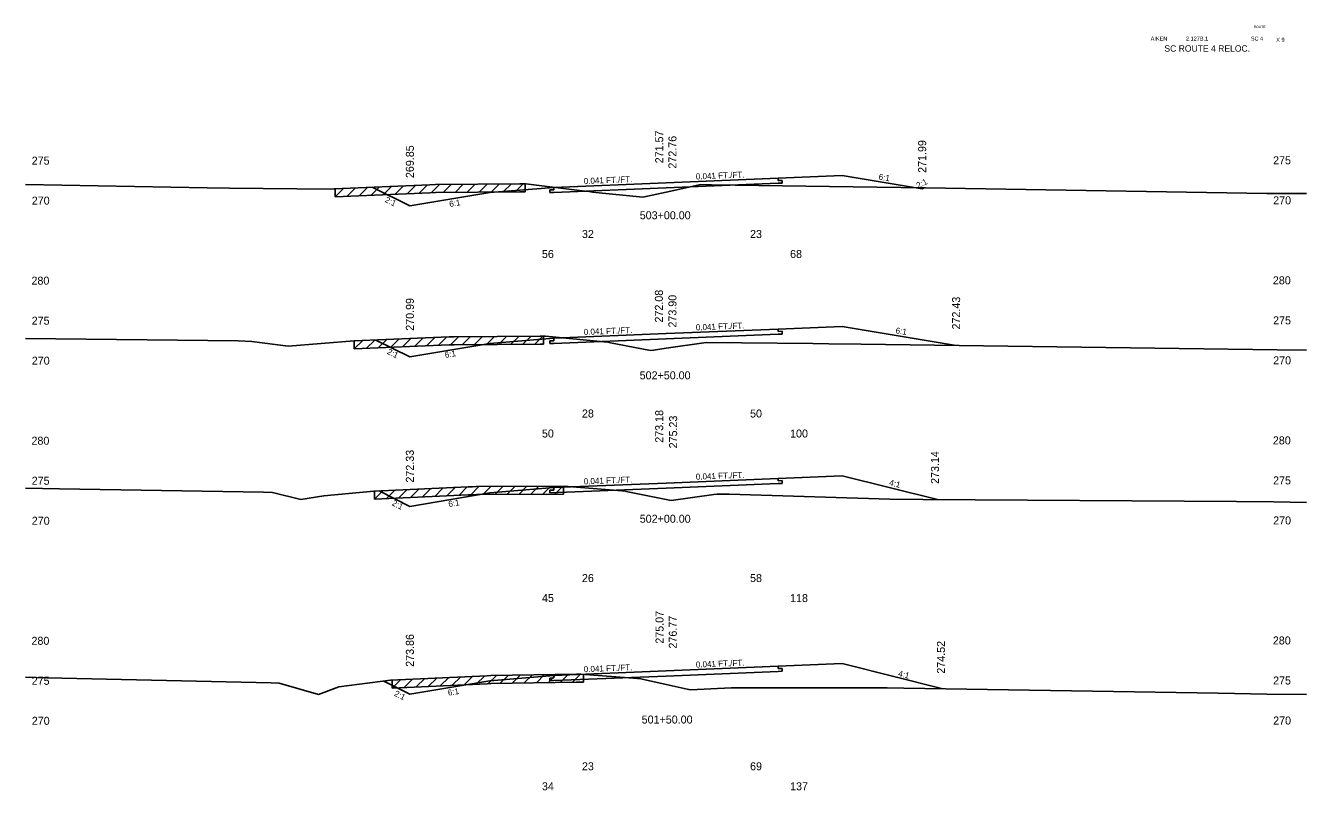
# Model space of a CAD drawing. Extents: x 2967 to 4323, y -3677 to -817.
# Drawn here: x 3188.8 to 3348.8, y -2753 to -2657.5 of the extents above; entities that cross this region are included whole.
import ezdxf

# ---------------------------------------------------------------- set-up
doc = ezdxf.new("R2010")
doc.units = 0
for name, color, linetype in [('Level 1', 7, 'Continuous'), ('Level 10', 7, 'Continuous'), ('Level 11', 7, 'Continuous'), ('Level 12', 7, 'Continuous'), ('Level 20', 7, 'Continuous'), ('Level 3', 7, 'Continuous'), ('Level 32', 7, 'Continuous'), ('Level 33', 7, 'Continuous'), ('Level 59', 7, 'Continuous'), ('Level 6', 7, 'Continuous'), ('Level 60', 7, 'Continuous'), ('Level 61', 7, 'Continuous'), ('Level 7', 7, 'Continuous')]:
    doc.layers.add(name, color=color, linetype=linetype)

msp = doc.modelspace()

# ---------------------------------------------------------------- linework, layer by layer
at = {"layer": 'Level 11'}
for p, q in [((3282.76, -2676.81), (3282.76, -2676.51)), ((3283.26, -2676.79), (3282.76, -2676.81)), ((3283.26, -2677.13), (3283.26, -2676.79)), ((3254.76, -2677.96), (3254.26, -2677.98)), ((3254.26, -2677.98), (3254.26, -2678.32)), ((3254.26, -2678.32), (3254.76, -2678.3)), ((3254.76, -2677.66), (3254.76, -2677.96)), ((3282.76, -2677.15), (3283.26, -2677.13)), ((3282.76, -2695.67), (3282.76, -2695.37)), ((3283.26, -2695.65), (3282.76, -2695.67)), ((3282.76, -2696.01), (3283.26, -2695.99)), ((3283.26, -2695.99), (3283.26, -2695.65)), ((3254.76, -2696.82), (3254.26, -2696.84)), ((3254.26, -2696.84), (3254.26, -2697.18)), ((3254.26, -2697.18), (3254.76, -2697.16)), ((3254.76, -2696.52), (3254.76, -2696.82)), ((3254.76, -2715.18), (3254.76, -2715.48)), ((3282.76, -2714.33), (3282.76, -2714.03)), ((3283.26, -2714.31), (3282.76, -2714.33)), ((3282.76, -2714.67), (3283.26, -2714.65)), ((3283.26, -2714.65), (3283.26, -2714.31)), ((3254.76, -2715.48), (3254.26, -2715.5)), ((3254.26, -2715.5), (3254.26, -2715.84)), ((3282.76, -2737.8), (3282.76, -2737.5)), ((3254.76, -2738.95), (3254.26, -2738.97)), ((3254.26, -2738.97), (3254.26, -2739.31)), ((3254.76, -2738.65), (3254.76, -2738.95)), ((3283.26, -2737.78), (3282.76, -2737.8)), ((3282.76, -2738.14), (3283.26, -2738.12)), ((3283.26, -2738.12), (3283.26, -2737.78)), ((3254.26, -2739.31), (3254.76, -2739.29))]:
    msp.add_line(p, q, dxfattribs=at)
at = {"layer": 'Level 12'}
for p, q in [((3268.76, -2677.72), (3254.76, -2678.3)), ((3282.76, -2677.15), (3268.76, -2677.72)), ((3268.76, -2696.58), (3254.76, -2697.16)), ((3282.76, -2696.01), (3268.76, -2696.58)), ((3268.76, -2715.25), (3282.76, -2714.67)), ((3254.26, -2715.84), (3268.76, -2715.25)), ((3254.76, -2739.29), (3268.76, -2738.72)), ((3268.76, -2738.72), (3282.76, -2738.14))]:
    msp.add_line(p, q, dxfattribs=at)
at = {"layer": 'Level 59'}
for p, q in [((3268.76, -2677.08), (3282.76, -2676.51)), ((3254.76, -2677.66), (3268.76, -2677.08)), ((3254.76, -2696.52), (3268.76, -2695.94)), ((3268.76, -2695.94), (3282.76, -2695.37)), ((3254.76, -2715.18), (3268.76, -2714.61)), ((3268.76, -2714.61), (3282.76, -2714.03)), ((3268.76, -2738.08), (3282.76, -2737.5)), ((3254.76, -2738.65), (3268.76, -2738.08))]:
    msp.add_line(p, q, dxfattribs=at)
at = {"layer": 'Level 6'}
for p, q in [((3282.76, -2676.51), (3290.76, -2676.18)), ((3246.76, -2678.32), (3254.76, -2677.66)), ((3282.76, -2695.37), (3290.76, -2695.04)), ((3246.76, -2697.18), (3254.76, -2696.52)), ((3246.76, -2715.85), (3254.76, -2715.18)), ((3282.76, -2714.03), (3290.76, -2713.71)), ((3282.76, -2737.5), (3290.76, -2737.17)), ((3246.76, -2739.32), (3254.76, -2738.65))]:
    msp.add_line(p, q, dxfattribs=at)
at = {"layer": 'Level 60'}
for p, q in [((3188.76, -2677.31), (3211.45, -2677.73)), ((3211.45, -2677.73), (3214.24, -2677.78)), ((3214.24, -2677.78), (3226.86, -2677.87)), ((3226.86, -2677.87), (3227.3, -2677.84)), ((3227.3, -2677.84), (3239.25, -2677.35)), ((3239.25, -2677.35), (3239.97, -2677.31)), ((3239.97, -2677.31), (3250.48, -2677.21)), ((3250.48, -2677.21), (3251.26, -2677.21)), ((3251.26, -2677.21), (3258.6, -2678.12)), ((3258.6, -2678.12), (3259.17, -2678.18)), ((3259.17, -2678.18), (3259.56, -2678.25)), ((3259.56, -2678.25), (3265.87, -2678.87)), ((3266.45, -2678.78), (3268.76, -2678.28)), ((3268.76, -2678.28), (3273.12, -2677.31)), ((3273.12, -2677.31), (3274.44, -2677.33)), ((3274.44, -2677.33), (3295.1, -2677.65)), ((3295.1, -2677.65), (3301.17, -2677.73)), ((3301.17, -2677.73), (3343.8, -2678.42)), ((3265.87, -2678.87), (3266.45, -2678.78)), ((3343.8, -2678.42), (3348.76, -2678.45)), ((3188.76, -2696.54), (3215.33, -2696.86)), ((3215.33, -2696.86), (3217.01, -2696.91)), ((3217.01, -2696.91), (3221.55, -2697.5)), ((3221.55, -2697.5), (3229.8, -2696.86)), ((3229.8, -2696.86), (3241.67, -2696.35)), ((3241.67, -2696.35), (3242.3, -2696.32)), ((3242.3, -2696.32), (3253.03, -2696.27)), ((3253.03, -2696.27), (3253.7, -2696.27)), ((3253.7, -2696.27), (3261.01, -2696.98)), ((3261.01, -2696.98), (3261.48, -2697.02)), ((3261.48, -2697.02), (3261.84, -2697.09)), ((3261.84, -2697.09), (3266.83, -2698.04)), ((3268.76, -2697.77), (3273.76, -2697.05)), ((3273.76, -2697.05), (3287.11, -2697.17)), ((3287.11, -2697.17), (3289.11, -2697.23)), ((3289.11, -2697.23), (3293.14, -2697.26)), ((3293.14, -2697.26), (3345.12, -2697.95)), ((3266.83, -2698.04), (3267.21, -2697.99)), ((3267.21, -2697.99), (3268.76, -2697.77)), ((3345.12, -2697.95), (3348.76, -2698.02)), ((3232.25, -2715.63), (3244.06, -2715.1)), ((3244.06, -2715.1), (3244.59, -2715.07)), ((3244.59, -2715.07), (3245.07, -2715.06)), ((3245.07, -2715.06), (3256.03, -2714.98)), ((3256.03, -2714.98), (3263.25, -2715.6)), ((3188.76, -2715.26), (3193, -2715.33)), ((3193, -2715.33), (3218.48, -2715.75)), ((3218.48, -2715.75), (3219.62, -2715.78)), ((3219.62, -2715.78), (3223.15, -2716.67)), ((3223.15, -2716.67), (3226.03, -2716.2)), ((3226.03, -2716.2), (3232.25, -2715.63)), ((3263.25, -2715.6), (3263.66, -2715.63)), ((3263.66, -2715.63), (3264.01, -2715.71)), ((3264.01, -2715.71), (3268.76, -2716.66)), ((3268.76, -2716.66), (3269.39, -2716.79)), ((3269.39, -2716.79), (3274.75, -2716.02)), ((3274.75, -2716.02), (3275.13, -2716.01)), ((3275.13, -2716.01), (3276.63, -2716.01)), ((3276.63, -2716.01), (3296.71, -2716.61)), ((3296.71, -2716.61), (3300.85, -2716.67)), ((3300.85, -2716.67), (3340.02, -2716.91)), ((3340.02, -2716.91), (3344.7, -2716.97)), ((3344.7, -2716.97), (3348.76, -2717.05)), ((3188.76, -2738.88), (3191.4, -2738.94)), ((3191.4, -2738.94), (3219.45, -2739.58)), ((3234.34, -2739.24), (3246.4, -2738.68)), ((3246.4, -2738.68), (3246.87, -2738.65)), ((3246.87, -2738.65), (3257.58, -2738.47)), ((3257.58, -2738.47), (3258.13, -2738.47)), ((3258.13, -2738.47), (3265.2, -2739.04)), ((3265.2, -2739.04), (3265.6, -2739.07)), ((3265.6, -2739.07), (3268.76, -2739.77)), ((3219.45, -2739.58), (3220.43, -2739.6)), ((3220.43, -2739.6), (3225.34, -2741.05)), ((3225.34, -2741.05), (3227.89, -2740.09)), ((3227.89, -2740.09), (3234.34, -2739.24)), ((3268.76, -2739.77), (3271.42, -2740.36)), ((3271.42, -2740.36), (3271.81, -2740.44)), ((3271.81, -2740.44), (3276.88, -2740.21)), ((3276.88, -2740.21), (3277.32, -2740.2)), ((3277.32, -2740.2), (3296.4, -2740.21)), ((3296.4, -2740.21), (3298.49, -2740.24)), ((3298.49, -2740.24), (3337.73, -2740.86)), ((3337.73, -2740.86), (3343.8, -2740.98)), ((3343.8, -2740.98), (3348.76, -2741.05))]:
    msp.add_line(p, q, dxfattribs=at)
at = {"layer": 'Level 61'}
for p, q in [((3228.45, -2677.79), (3227.41, -2678.84)), ((3227.41, -2677.84), (3227.41, -2678.84)), ((3227.41, -2678.84), (3239.25, -2678.35)), ((3229.95, -2677.73), (3228.91, -2678.77)), ((3231.45, -2677.67), (3230.41, -2678.71)), ((3232.96, -2677.61), (3231.91, -2678.65)), ((3234.46, -2677.54), (3233.41, -2678.59)), ((3235.96, -2677.48), (3234.91, -2678.52)), ((3237.46, -2677.42), (3236.42, -2678.46)), ((3238.96, -2677.36), (3237.92, -2678.4)), ((3239.25, -2678.35), (3239.97, -2678.31)), ((3240.45, -2677.31), (3239.42, -2678.34)), ((3239.97, -2678.31), (3250.48, -2678.21)), ((3241.93, -2677.3), (3240.92, -2678.31)), ((3243.43, -2677.28), (3242.42, -2678.29)), ((3244.93, -2677.27), (3243.92, -2678.28)), ((3246.43, -2677.25), (3245.42, -2678.26)), ((3247.94, -2677.24), (3246.92, -2678.25)), ((3249.44, -2677.22), (3248.43, -2678.23)), ((3250.93, -2677.21), (3249.93, -2678.22)), ((3250.48, -2678.21), (3251.18, -2678.21)), ((3251.18, -2678.21), (3251.18, -2677.21)), ((3230.87, -2696.81), (3229.82, -2697.85)), ((3229.82, -2696.85), (3229.82, -2697.85)), ((3229.82, -2697.85), (3241.67, -2697.35)), ((3232.37, -2696.74), (3231.32, -2697.79)), ((3233.87, -2696.68), (3232.82, -2697.73)), ((3235.37, -2696.62), (3234.33, -2697.66)), ((3236.88, -2696.55), (3235.83, -2697.6)), ((3238.38, -2696.49), (3237.33, -2697.53)), ((3239.88, -2696.42), (3238.83, -2697.47)), ((3241.38, -2696.36), (3240.34, -2697.4)), ((3241.67, -2697.35), (3242.3, -2697.32)), ((3242.86, -2696.31), (3241.84, -2697.34)), ((3242.3, -2697.32), (3253.03, -2697.27)), ((3244.35, -2696.31), (3243.34, -2697.31)), ((3245.85, -2696.3), (3244.84, -2697.31)), ((3247.35, -2696.3), (3246.35, -2697.3)), ((3248.85, -2696.29), (3247.85, -2697.29)), ((3250.36, -2696.28), (3249.35, -2697.29)), ((3251.86, -2696.28), (3250.85, -2697.28)), ((3253.36, -2696.27), (3252.36, -2697.27)), ((3253.03, -2697.27), (3253.44, -2697.27)), ((3253.44, -2697.27), (3253.44, -2696.27)), ((3242.41, -2715.17), (3241.36, -2716.22)), ((3243.91, -2715.1), (3242.86, -2716.15)), ((3245.38, -2715.06), (3244.36, -2716.08)), ((3246.87, -2715.05), (3245.86, -2716.06)), ((3248.37, -2715.04), (3247.36, -2716.05)), ((3249.87, -2715.03), (3248.86, -2716.03)), ((3251.37, -2715.02), (3250.36, -2716.02)), ((3252.87, -2715), (3251.87, -2716.01)), ((3254.37, -2714.99), (3253.37, -2716)), ((3255.88, -2714.98), (3254.87, -2715.99)), ((3255.95, -2715.98), (3255.95, -2714.98)), ((3233.4, -2715.58), (3232.35, -2716.62)), ((3232.35, -2715.62), (3232.35, -2716.62)), ((3232.35, -2716.62), (3244.06, -2716.1)), ((3234.9, -2715.51), (3233.85, -2716.56)), ((3236.4, -2715.44), (3235.35, -2716.49)), ((3237.9, -2715.37), (3236.85, -2716.42)), ((3239.4, -2715.31), (3238.36, -2716.35)), ((3240.9, -2715.24), (3239.86, -2716.29)), ((3244.06, -2716.1), (3244.59, -2716.07)), ((3244.59, -2716.07), (3245.07, -2716.06)), ((3245.07, -2716.06), (3255.95, -2715.98)), ((3235.61, -2739.18), (3234.56, -2740.23)), ((3237.11, -2739.11), (3236.06, -2740.16)), ((3238.61, -2739.04), (3237.56, -2740.09)), ((3240.11, -2738.97), (3239.06, -2740.02)), ((3241.61, -2738.9), (3240.56, -2739.95)), ((3243.11, -2738.83), (3242.06, -2739.88)), ((3244.61, -2738.76), (3243.56, -2739.81)), ((3246.11, -2738.69), (3245.06, -2739.74)), ((3247.59, -2738.64), (3246.56, -2739.67)), ((3249.08, -2738.62), (3248.06, -2739.63)), ((3250.58, -2738.59), (3249.56, -2739.61)), ((3252.08, -2738.56), (3251.06, -2739.58)), ((3253.58, -2738.54), (3252.56, -2739.56)), ((3255.08, -2738.51), (3254.06, -2739.53)), ((3256.58, -2738.49), (3255.56, -2739.51)), ((3258.08, -2738.47), (3257.06, -2739.48)), ((3258.46, -2739.49), (3258.46, -2738.49)), ((3234.56, -2739.23), (3234.56, -2740.23)), ((3234.56, -2740.23), (3246.4, -2739.68)), ((3246.4, -2739.68), (3246.87, -2739.65)), ((3246.87, -2739.65), (3257.58, -2739.47)), ((3257.58, -2739.47), (3258.13, -2739.47)), ((3258.13, -2739.47), (3258.46, -2739.49))]:
    msp.add_line(p, q, dxfattribs=at)
at = {"layer": 'Level 7'}
for p, q in [((3290.76, -2676.18), (3300.76, -2677.85)), ((3232.06, -2677.64), (3236.76, -2679.99)), ((3236.76, -2679.99), (3246.76, -2678.32)), ((3300.76, -2677.85), (3300.99, -2677.73)), ((3290.76, -2695.04), (3305, -2697.42)), ((3232.53, -2696.74), (3236.76, -2698.85)), ((3236.76, -2698.85), (3246.76, -2697.18)), ((3290.76, -2713.71), (3302.67, -2716.68)), ((3232.92, -2715.6), (3236.76, -2717.52)), ((3236.76, -2717.52), (3246.76, -2715.85)), ((3290.76, -2737.17), (3303.33, -2740.32)), ((3233.49, -2739.35), (3236.76, -2740.98)), ((3236.76, -2740.98), (3246.76, -2739.32))]:
    msp.add_line(p, q, dxfattribs=at)

# ---------------------------------------------------------------- texts
at = {"layer": 'Level 1'}
for s, p in [('32', (3258.26, -2683.99)), ('23', (3279.26, -2683.99)), ('56', (3253.26, -2686.49)), ('68', (3284.26, -2686.49)), ('28', (3258.26, -2706.42)), ('50', (3279.26, -2706.42)), ('50', (3253.26, -2708.92)), ('100', (3284.26, -2708.92)), ('26', (3258.26, -2726.98)), ('58', (3279.26, -2726.98)), ('45', (3253.26, -2729.48)), ('118', (3284.26, -2729.48)), ('23', (3258.26, -2750.5)), ('69', (3279.26, -2750.5)), ('34', (3253.26, -2753)), ('137', (3284.26, -2753))]:
    msp.add_text(s, height=1, dxfattribs=at).set_placement(p)
at = {"layer": 'Level 10'}
for s, p in [('271.57', (3268.41, -2674.66)), ('272.08', (3268.37, -2694.55)), ('273.18', (3268.41, -2709.57)), ('275.07', (3268.45, -2734.68))]:
    msp.add_text(s, height=1, rotation=90, dxfattribs=at).set_placement(p)
for s, p in [('503+00.00', (3265.48, -2681.65)), ('502+50.00', (3265.47, -2701.65)), ('502+00.00', (3265.48, -2719.57)), ('501+50.00', (3265.72, -2744.66))]:
    msp.add_text(s, height=1, dxfattribs=at).set_placement(p)
at = {"layer": 'Level 20'}
for s, height, p in [('ROUTE', 0.3, (3342.19, -2657.76)), ('AIKEN', 0.5, (3329.31, -2659.32)), (' 2.127B.1', 0.5, (3333.53, -2659.32)), ('SC 4', 0.5, (3341.82, -2659.32)), ('X 9', 0.5, (3344.99, -2659.47)), ('SC ROUTE 4 RELOC.', 0.8, (3331.02, -2660.71))]:
    msp.add_text(s, height=height, dxfattribs=at).set_placement(p)
at = {"layer": 'Level 3'}
for s, p in [(' 275', (3189.15, -2674.82)), (' 275', (3344.23, -2674.78)), (' 270', (3189.16, -2679.82)), (' 270', (3344.24, -2679.78)), (' 280', (3189.12, -2689.82)), (' 280', (3344.2, -2689.78)), (' 275', (3189.15, -2694.82)), (' 275', (3344.23, -2694.78)), (' 270', (3189.16, -2699.82)), (' 270', (3344.24, -2699.78)), (' 280', (3344.2, -2709.78)), (' 280', (3189.12, -2709.82)), (' 275', (3189.15, -2714.82)), (' 275', (3344.23, -2714.78)), (' 270', (3189.16, -2719.82)), (' 270', (3344.24, -2719.78)), (' 280', (3189.12, -2734.82)), (' 280', (3344.2, -2734.78)), (' 275', (3189.15, -2739.82)), (' 275', (3344.23, -2739.78)), (' 270', (3189.16, -2744.82)), (' 270', (3344.24, -2744.78))]:
    msp.add_text(s, height=1, dxfattribs=at).set_placement(p)
at = {"layer": 'Level 32'}
for s, rotation, p in [('0.041 FT./FT.', 2.3478, (3258.5, -2677.25)), ('0.041 FT./FT.', 2.3478, (3272.5, -2676.68)), ('6:1', 350.5377, (3295.28, -2676.68)), ('2:1', 26.5651, (3300.26, -2677.82)), ('2:1', 333.435, (3233.57, -2679.46)), ('6:1', 9.4623, (3241.75, -2680.12)), ('0.041 FT./FT.', 2.3478, (3258.5, -2696.11)), ('0.041 FT./FT.', 2.3478, (3272.5, -2695.54)), ('6:1', 350.5377, (3297.4, -2695.89)), ('2:1', 333.435, (3233.84, -2698.44)), ('6:1', 9.4623, (3241.19, -2698.98)), ('0.041 FT./FT.', 2.3478, (3272.5, -2714.2)), ('0.041 FT./FT.', 2.3478, (3258.5, -2714.78)), ('4:1', 345.9638, (3296.59, -2714.88)), ('2:1', 333.435, (3234.45, -2717.35)), ('6:1', 9.4623, (3241.64, -2717.61)), ('0.041 FT./FT.', 2.3478, (3258.5, -2738.25)), ('0.041 FT./FT.', 2.3478, (3272.5, -2737.67)), ('4:1', 345.9638, (3297.71, -2738.73)), ('2:1', 333.435, (3234.73, -2741.15)), ('6:1', 9.4623, (3241.57, -2741.19))]:
    msp.add_text(s, height=0.75, rotation=rotation, dxfattribs=at).set_placement(p)
at = {"layer": 'Level 33'}
for s, p in [('271.99', (3301.26, -2675.85)), ('269.85', (3237.26, -2676.5)), ('270.99', (3237.26, -2695.58)), ('272.43', (3305.5, -2695.42)), ('272.33', (3237.26, -2714.55)), ('273.14', (3302.86, -2714.72)), ('273.86', (3237.26, -2737.57)), ('274.52', (3303.61, -2738.43))]:
    msp.add_text(s, height=1, rotation=90, dxfattribs=at).set_placement(p)
at = {"layer": 'Level 59'}
for s, p in [(' 272.76', (3270.06, -2675.69)), (' 273.90', (3270.06, -2695.55)), (' 275.23', (3270.15, -2710.65)), (' 276.77', (3270.11, -2735.66))]:
    msp.add_text(s, height=1, rotation=90, dxfattribs=at).set_placement(p)

doc.saveas('drawing.dxf')
